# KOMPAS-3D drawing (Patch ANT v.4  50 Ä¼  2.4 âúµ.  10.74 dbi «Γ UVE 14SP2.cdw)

Referenced files in G:\: Patch ANT v.4  50 Ом от uve.cdw
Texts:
  высота над рефлектором 7мм
  50 ом Патч антенна на 2.4...2.5 ГГц
  Точка нулевого
  потенциала
  Ø Стойки 5mm
  Толщина патча 0,5 мм
  Точка запитки Ø 1,5 mm
  Type N
  Ø 2mm
  Знак неуказанной шероховатости
  Параметр неуказанной шероховатости
  Patch ANT v.4  50 Ом
  https://www.lan23.ru/forum/node/851/page32
  https://www.lan23.ru/forum/node/851/page32-
  UVE
  Patch ANT v.4  50 Ом  2,4Ггц.10,74 dbi.
Dimensions and other numbers on the sheet: 52,75; 50,5; 80; 74,5; 53,25; 18,24; 13; 70,88; 44,07; 97,69; 160; 21,75; 59; 26,75; 54,5; 5,5; 32,25; 4; 1:1; 1; 2,4Ггц.10,74 dbi.; 2022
